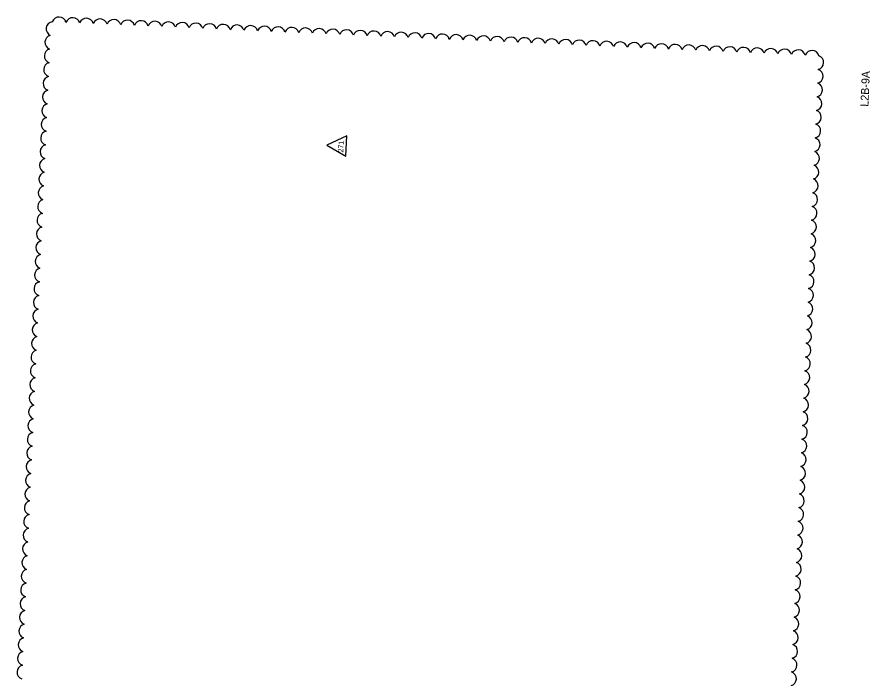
# Model space of a CAD drawing. Extents: x 928596 to 929473, y 645293 to 646588.
# Drawn here: x 928621 to 929473, y 645927 to 646588 of the extents above; entities that cross this region are included whole.
import ezdxf

# ---------------------------------------------------------------- set-up
doc = ezdxf.new("R2010")
doc.units = 0
for name, color, linetype in [('Cloud_dp', 7, 'Continuous'), ('LeaderLine_dp', 7, 'Continuous'), ('TextBLStation', 7, 'Continuous'), ('TextShtNo', 7, 'Continuous')]:
    doc.layers.add(name, color=color, linetype=linetype)

msp = doc.modelspace()

# ---------------------------------------------------------------- linework, layer by layer
at = {"layer": 'Cloud_dp'}
msp.add_lwpolyline([(928930.46, 646460.43), (928949.52, 646449.44), (928950.42, 646469.69)], close=True, dxfattribs=at)
at = {"layer": 'LeaderLine_dp'}
for centre, radius, start, end in [((928657.25, 646576.49), 7.17, 99.21011, 244.21011), ((928662.85, 646581.11), 7.18, 14.96475, 159.96475), ((928676.52, 646580.51), 7.18, 14.96475, 159.96475), ((928690.2, 646579.9), 7.18, 14.96475, 159.96475), ((928703.87, 646579.3), 7.18, 14.96475, 159.96475), ((928717.55, 646578.69), 7.18, 14.96475, 159.96475), ((928731.23, 646578.09), 7.18, 14.96475, 159.96475), ((928744.9, 646577.48), 7.18, 14.96475, 159.96475), ((928758.58, 646576.87), 7.18, 14.96475, 159.96475), ((928772.26, 646576.27), 7.18, 14.96475, 159.96475), ((928785.93, 646575.66), 7.18, 14.96475, 159.96475), ((928799.61, 646575.06), 7.18, 14.96475, 159.96475), ((928813.29, 646574.45), 7.18, 14.96475, 159.96475), ((928826.96, 646573.85), 7.18, 14.96475, 159.96475), ((928840.64, 646573.24), 7.18, 14.96475, 159.96475), ((928854.31, 646572.64), 7.18, 14.96475, 159.96475), ((928867.99, 646572.03), 7.18, 14.96475, 159.96475), ((928881.67, 646571.42), 7.18, 14.96475, 159.96475), ((928895.34, 646570.82), 7.18, 14.96475, 159.96475), ((928909.02, 646570.21), 7.18, 14.96475, 159.96475), ((928922.7, 646569.61), 7.18, 14.96475, 159.96475), ((928936.37, 646569), 7.18, 14.96475, 159.96475), ((928950.05, 646568.4), 7.18, 14.96475, 159.96475), ((928963.73, 646567.79), 7.18, 14.96475, 159.96475), ((928977.4, 646567.19), 7.18, 14.96475, 159.96475), ((928655.98, 646563.1), 7.18, 104.96475, 249.96475), ((928991.08, 646566.58), 7.18, 14.96475, 159.96475), ((929004.76, 646565.97), 7.18, 14.96475, 159.96475), ((929018.43, 646565.37), 7.18, 14.96475, 159.96475), ((929032.11, 646564.76), 7.18, 14.96475, 159.96475), ((929045.78, 646564.16), 7.18, 14.96475, 159.96475), ((929059.46, 646563.55), 7.18, 14.96475, 159.96475), ((929073.14, 646562.95), 7.18, 14.96475, 159.96475), ((929086.81, 646562.34), 7.18, 14.96475, 159.96475), ((929100.49, 646561.74), 7.18, 14.96475, 159.96475), ((929114.17, 646561.13), 7.18, 14.96475, 159.96475), ((929127.84, 646560.52), 7.18, 14.96475, 159.96475), ((929141.52, 646559.92), 7.18, 14.96475, 159.96475), ((929155.2, 646559.31), 7.18, 14.96475, 159.96475), ((929168.87, 646558.71), 7.18, 14.96475, 159.96475), ((929182.55, 646558.1), 7.18, 14.96475, 159.96475), ((929196.22, 646557.5), 7.18, 14.96475, 159.96475), ((929209.9, 646556.89), 7.18, 14.96475, 159.96475), ((929223.58, 646556.29), 7.18, 14.96475, 159.96475), ((929237.25, 646555.68), 7.18, 14.96475, 159.96475), ((929250.93, 646555.07), 7.18, 14.96475, 159.96475), ((929264.61, 646554.47), 7.18, 14.96475, 159.96475), ((929278.28, 646553.86), 7.18, 14.96475, 159.96475), ((929291.96, 646553.26), 7.18, 14.96475, 159.96475), ((929305.64, 646552.65), 7.18, 14.96475, 159.96475), ((929319.31, 646552.05), 7.18, 14.96475, 159.96475), ((929332.99, 646551.44), 7.18, 14.96475, 159.96475), ((929346.67, 646550.84), 7.18, 14.96475, 159.96475), ((929360.34, 646550.23), 7.18, 14.96475, 159.96475), ((928655.38, 646549.43), 7.18, 104.96475, 249.96475), ((929374.02, 646549.62), 7.18, 14.96475, 159.96475), ((929387.69, 646549.02), 7.18, 14.96475, 159.96475), ((929401.37, 646548.41), 7.18, 14.96475, 159.96475), ((929415.05, 646547.81), 7.18, 14.96475, 159.96475), ((929419.52, 646542.92), 7.18, 284.96475, 69.96475), ((928654.77, 646535.75), 7.18, 104.96475, 249.96475), ((929418.92, 646529.24), 7.18, 284.96475, 69.96475), ((928654.17, 646522.07), 7.18, 104.96475, 249.96475), ((928653.56, 646508.4), 7.18, 104.96475, 249.96475), ((929418.31, 646515.57), 7.18, 284.96475, 69.96475), ((929417.71, 646501.89), 7.18, 284.96475, 69.96475), ((928652.96, 646494.72), 7.18, 104.96475, 249.96475), ((929417.1, 646488.21), 7.18, 284.96475, 69.96475), ((928652.35, 646481.05), 7.18, 104.96475, 249.96475), ((929416.49, 646474.54), 7.18, 284.96475, 69.96475), ((928651.75, 646467.37), 7.18, 104.96475, 249.96475), ((929415.89, 646460.86), 7.18, 284.96475, 69.96475), ((928651.14, 646453.69), 7.18, 104.96475, 249.96475), ((928650.53, 646440.02), 7.18, 104.96475, 249.96475), ((929415.28, 646447.18), 7.18, 284.96475, 69.96475), ((929414.68, 646433.51), 7.18, 284.96475, 69.96475), ((928649.93, 646426.34), 7.18, 104.96475, 249.96475), ((929414.07, 646419.83), 7.18, 284.96475, 69.96475), ((928649.32, 646412.66), 7.18, 104.96475, 249.96475), ((929413.47, 646406.15), 7.18, 284.96475, 69.96475), ((928648.72, 646398.99), 7.18, 104.96475, 249.96475), ((929412.86, 646392.48), 7.18, 284.96475, 69.96475), ((928648.11, 646385.31), 7.18, 104.96475, 249.96475), ((928647.51, 646371.63), 7.18, 104.96475, 249.96475), ((929412.26, 646378.8), 7.18, 284.96475, 69.96475), ((929411.65, 646365.12), 7.18, 284.96475, 69.96475), ((928646.9, 646357.96), 7.18, 104.96475, 249.96475), ((929411.04, 646351.45), 7.18, 284.96475, 69.96475), ((928646.3, 646344.28), 7.18, 104.96475, 249.96475), ((929410.44, 646337.77), 7.18, 284.96475, 69.96475), ((928645.69, 646330.61), 7.18, 104.96475, 249.96475), ((929409.83, 646324.1), 7.18, 284.96475, 69.96475), ((928645.08, 646316.93), 7.18, 104.96475, 249.96475), ((928644.48, 646303.25), 7.18, 104.96475, 249.96475), ((929409.23, 646310.42), 7.18, 284.96475, 69.96475), ((929408.62, 646296.74), 7.18, 284.96475, 69.96475), ((928643.87, 646289.58), 7.18, 104.96475, 249.96475), ((929408.02, 646283.07), 7.18, 284.96475, 69.96475), ((928643.27, 646275.9), 7.18, 104.96475, 249.96475), ((929407.41, 646269.39), 7.18, 284.96475, 69.96475), ((928642.66, 646262.22), 7.18, 104.96475, 249.96475), ((929406.81, 646255.71), 7.18, 284.96475, 69.96475), ((928642.06, 646248.55), 7.18, 104.96475, 249.96475), ((929406.2, 646242.04), 7.18, 284.96475, 69.96475), ((928641.45, 646234.87), 7.18, 104.96475, 249.96475), ((929405.59, 646228.36), 7.18, 284.96475, 69.96475), ((928640.85, 646221.19), 7.18, 104.96475, 249.96475), ((929404.99, 646214.68), 7.18, 284.96475, 69.96475), ((928640.24, 646207.52), 7.18, 104.96475, 249.96475), ((928639.63, 646193.84), 7.18, 104.96475, 249.96475), ((929404.38, 646201.01), 7.18, 284.96475, 69.96475), ((929403.78, 646187.33), 7.18, 284.96475, 69.96475), ((928639.03, 646180.16), 7.18, 104.96475, 249.96475), ((929403.17, 646173.66), 7.18, 284.96475, 69.96475), ((928638.42, 646166.49), 7.18, 104.96475, 249.96475), ((929402.57, 646159.98), 7.18, 284.96475, 69.96475), ((928637.82, 646152.81), 7.18, 104.96475, 249.96475), ((929401.96, 646146.3), 7.18, 284.96475, 69.96475), ((928637.21, 646139.14), 7.18, 104.96475, 249.96475), ((928636.61, 646125.46), 7.18, 104.96475, 249.96475), ((929401.36, 646132.63), 7.18, 284.96475, 69.96475), ((929400.75, 646118.95), 7.18, 284.96475, 69.96475), ((928636, 646111.78), 7.18, 104.96475, 249.96475), ((929400.14, 646105.27), 7.18, 284.96475, 69.96475), ((928635.4, 646098.11), 7.18, 104.96475, 249.96475), ((929399.54, 646091.6), 7.18, 284.96475, 69.96475), ((928634.79, 646084.43), 7.18, 104.96475, 249.96475), ((929398.93, 646077.92), 7.18, 284.96475, 69.96475), ((928634.18, 646070.75), 7.18, 104.96475, 249.96475), ((928633.58, 646057.08), 7.18, 104.96475, 249.96475), ((929398.33, 646064.24), 7.18, 284.96475, 69.96475), ((929397.72, 646050.57), 7.18, 284.96475, 69.96475), ((928632.97, 646043.4), 7.18, 104.96475, 249.96475), ((929397.12, 646036.89), 7.18, 284.96475, 69.96475), ((928632.37, 646029.72), 7.18, 104.96475, 249.96475), ((929396.51, 646023.21), 7.18, 284.96475, 69.96475), ((928631.76, 646016.05), 7.18, 104.96475, 249.96475), ((929395.91, 646009.54), 7.18, 284.96475, 69.96475), ((928631.16, 646002.37), 7.18, 104.96475, 249.96475), ((928630.55, 645988.7), 7.18, 104.96475, 249.96475), ((929395.3, 645995.86), 7.18, 284.96475, 69.96475), ((929394.69, 645982.19), 7.18, 284.96475, 69.96475), ((928629.95, 645975.02), 7.18, 104.96475, 249.96475), ((929394.09, 645968.51), 7.18, 284.96475, 69.96475), ((928629.34, 645961.34), 7.18, 104.96475, 249.96475), ((929393.48, 645954.83), 7.18, 284.96475, 69.96475), ((928628.73, 645947.67), 7.18, 104.96475, 249.96475), ((929392.88, 645941.16), 7.18, 284.96475, 69.96475), ((928628.13, 645933.99), 7.18, 104.96475, 249.96475), ((929392.27, 645927.48), 7.18, 284.96475, 69.96475)]:
    msp.add_arc(centre, radius, start, end, dxfattribs=at)

# ---------------------------------------------------------------- texts
at = {"layer": 'TextBLStation'}
msp.add_text('271', height=5, rotation=87.46475, dxfattribs=at).set_placement((928946.72, 646452.99))
at = {"layer": 'TextShtNo'}
msp.add_text('L2B-9A', height=8, rotation=87.46475, dxfattribs=at).set_placement((929471.36, 646498.64))

doc.saveas('drawing.dxf')
